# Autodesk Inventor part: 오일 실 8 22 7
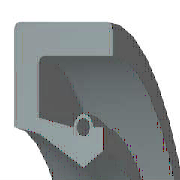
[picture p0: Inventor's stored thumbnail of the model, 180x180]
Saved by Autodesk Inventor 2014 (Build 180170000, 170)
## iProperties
IsCustomPart: 1
Created: 2012-02
Part Number: 오일 실 8 22 7
Material: 고무
Description: 오일-실
Document SubType Name: Modeling
Standard: KS B 2804
Designer: test
Standards Organization: KS
Language: ko-KR
Size Designation: S - 8 22 7
Categories: <MemberInstance><Categories><Category DisplayName="샤프트 부품" InternalName="7f7aeb1f-a693-4053-b835-cee3144e0d98" Mnemonic="SHFT"><Category DisplayName="실링" Intern
Density: 0.93 g/cm^3
Appearance: Rubber - Black - Version 1.1
Mass: 1.07912 g
Surface Area: 17.6852 cm^2
Volume: 1.16034 cm^3
Author: test
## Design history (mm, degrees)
revolve "본체" stored, may be unused: angle "d17" = 90 deg
revolve "스프링1" stored, may be unused: angle "d18" = 90 deg
body "Solid1"
sketch "스케치1"
  geometry: L1 (0, 11)-(7, 11); L2 (7, 11)-(7, 9.75); L3 (7, 9.75)-(1.75, 9.75); L4 (0, 11)-(0, 6.1); L5 (0, 6.1)-(1.75, 5.75); L6 (1.75, 5.75)-(4.9, 4); L7 (4.9, 4)-(0, 4); L8 (6.3, 4.875)-(6.3, 6.1); L9 (0, 0)-(9.586, 0) reference; L10 (4.9, 4)-(6.3, 4.875); L11 (0, 18)-(0, -3) reference; L12 (-1.917, 0)-(11.503, 0) reference; L13 (4.2, 6.1)-(1.75, 6.59); L14 (1.75, 6.59)-(1.75, 9.75); L15 (6.3, 6.1)-(5.6, 6.1); C1 r 0.455 at (4.9, 6.1); A1 r 0.7 centre (4.9, 6.1) between (5.6, 6.1) and (4.2, 6.1)
  constraints: 26 end point, 5 horizontal alignment, 4 perpendicular, 2 centre point, 2 collinear, 2 horizontal, 2 parallel, 2 point on circle, 2 point on line, 2 vertical alignment, 1 coincident
  dimensions: "d0" = 22 diameter of L1 L9 (= SD2); "d1" = 9.75 diameter of L8.start L9 (= ABDM); "d2" = 1.25 distance of L1.end L2.end (computed from SD); "d3" = 0.91 diameter of C1 (= SPDI); "d4" = 1.4 diameter of A1 (= SPDA); "d5" = 8 diameter of L6.end L9 (= NND); "d6" = 11.5 diameter of L5.end L9 (= TKDM); "d7" = 12.2 diameter of L4.end L9 (= HLDM); "d8" = 4.9 distance from line of C1.centre L4 (= SPDST); "d9" = 6.3 distance between parallel lines of L8 L4 (= SDI); "d10" = 7 distance between parallel lines of L2 L4 (= SWDT); "d12" = 1.75 distance between parallel lines of L14 L4 (= SD)
fillet "모깎기1" dims "d11" = 0.3 (= RR)
other parameters: "SD2" = 22 [user parameter; used in 1 equation term], "SWDT" = 7 [user parameter; used in 1 equation term], "RR" = 0.3 [user parameter; used in 1 equation term], "SD" = 1.75 [user parameter; used in 2 equation terms], "NND" = 8 [user parameter; used in 1 equation term], "SPDA" = 1.4 [user parameter; used in 1 equation term], "SPDI" = 0.91 [user parameter; used in 1 equation term], "TKDM" = 11.5 [user parameter; used in 1 equation term], "HLDM" = 12.2 [user parameter; used in 1 equation term], "ABDM" = 9.75 [user parameter; used in 1 equation term], "SDI" = 6.3 [user parameter; used in 1 equation term], "SPDST" = 4.9 [user parameter; used in 1 equation term], "d13" = 0, "d14" = 0, "d15" = 0, "LAB" = 0.35 [user parameter]
